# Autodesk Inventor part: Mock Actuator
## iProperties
Shininess: 64.0
Length Units: 11272
Angle Units: 11279
Time Units: 11290
Mass Units: 11286
Length Display Precision: 3
Angle Display Precision: 2
Compacted: True
Part Number: Mock Actuator
Document SubType Name: Modeling
Created: 2004-04
Designer: jpittman
Manufacturer: Standard
Standards Organization: Custom
Density: 0.0
Volumn: 0.0
Area: 0.0
PropertySet Name: Model Information
Control State: 0
Master: False
Checked Out: False
Author: jpittman
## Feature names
1. Extrusion1
